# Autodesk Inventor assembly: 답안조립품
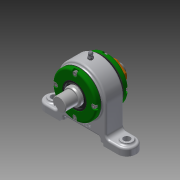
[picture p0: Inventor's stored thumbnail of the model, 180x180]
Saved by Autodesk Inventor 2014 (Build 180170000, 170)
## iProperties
Created: 2019-05
Part Number: 답안조립품
Document SubType Name: Assembly
Designer: kh
Author: kh
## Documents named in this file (13)
- C:\Users\kh\Desktop\490504V1049\답안조립품.iam
- C:\Users\kh\Desktop\490504V1049\본체.ipt
- C:\Users\kh\Desktop\490504V1049\개스킷.ipt
- C:\Users\kh\Desktop\490504V1049\그리스니플 M6.ipt
- 그리스니플  M6.ipt
- C:\Users\kh\Desktop\490504V1049\그리스니플개스킷.ipt
- C:\Users\kh\Desktop\490504V1049\베어링너트.ipt
- C:\Users\kh\Desktop\490504V1049\볼트 M4.ipt
- C:\Users\kh\Desktop\490504V1049\앵귤러 볼 베어링 7205.ipt
- C:\Users\kh\Desktop\490504V1049\오일 실 28 40 5 B.ipt
- C:\Users\kh\Desktop\490504V1049\축.ipt
- C:\Users\kh\Desktop\490504V1049\칼라.ipt
- C:\Users\kh\Desktop\490504V1049\커버.ipt
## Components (4 placed, 3 different names)
1. 개스킷:1 — Insert:6, Insert:7
2. 그리스니플  M6:1 — Insert:13
3. 그리스니플개스킷:1 — Insert:12, Insert:13
4. 개스킷:2 — Insert:8, Insert:9
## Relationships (6: Insert 6)
- Insert:6: 개스킷:1
- Insert:7: 개스킷:1
- Insert:8: 개스킷:2
- Insert:9: 개스킷:2
- Insert:12: 그리스니플개스킷:1
- Insert:13: 그리스니플  M6:1 ↔ 그리스니플개스킷:1
